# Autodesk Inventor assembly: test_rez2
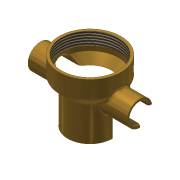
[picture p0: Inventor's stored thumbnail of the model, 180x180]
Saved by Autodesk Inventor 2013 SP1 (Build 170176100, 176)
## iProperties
Created: 2013-01
Part Number: test_rez2
Document SubType Name: Assembly
Designer: pospisil
Author: pospisil
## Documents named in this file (2)
- M:\Osobni\Václav Pospíšil\Ostatni_pro_topeni\Test render ventil\test_rez2.iam
- M:\Osobni\Václav Pospíšil\Ostatni_pro_topeni\Test render ventil\telo2.ipt
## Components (1 placed, 1 different names)
1. telo2:1
